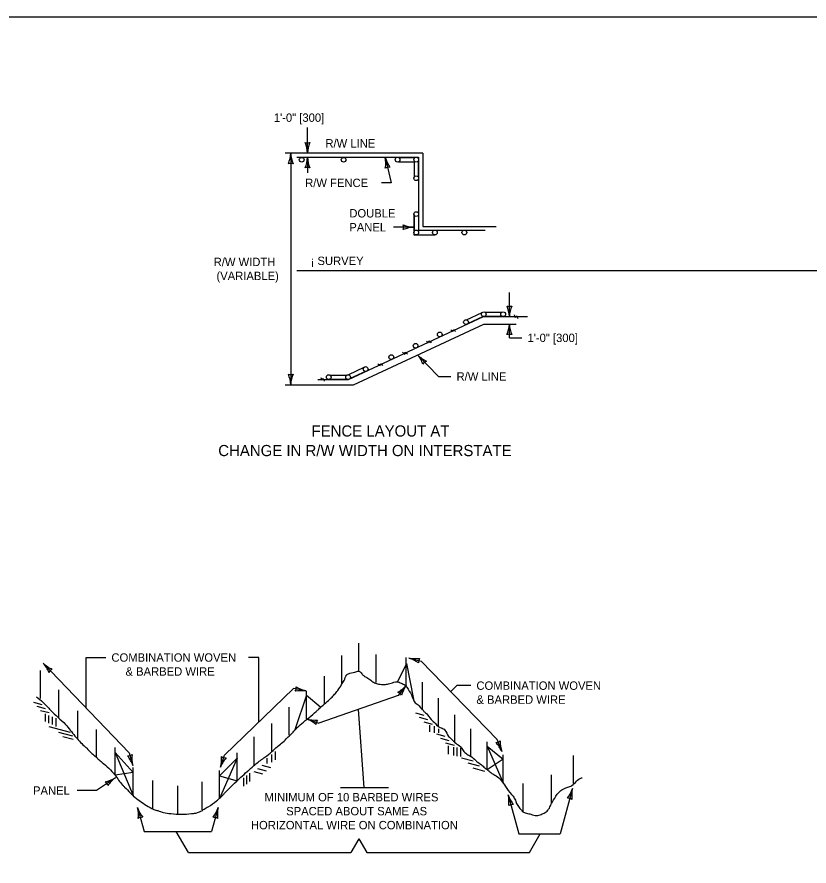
# Model space of a CAD drawing. Extents: x 49991.4 to 50021, y 49987.6 to 50011.4.
# Drawn here: x 50005.57 to 50011.24, y 49992.92 to 49999 of the extents above; entities that cross this region are included whole.
import ezdxf

# ---------------------------------------------------------------- set-up
doc = ezdxf.new("R2010")
doc.units = 0
for name, color, linetype in [('Level 1', 7, 'Continuous'), ('Level 2', 7, 'Continuous'), ('Level 3', 7, 'Continuous'), ('Level 5', 7, 'Continuous')]:
    doc.layers.add(name, color=color, linetype=linetype)

msp = doc.modelspace()

# ---------------------------------------------------------------- linework, layer by layer
at = {"layer": 'Level 1'}
for p, q in [((50008.4738, 49998.0252), (50007.4893, 49998.0252)), ((50008.4738, 49998.0252), (50008.4738, 49997.5002)), ((50007.5736, 49997.9952), (50008.4436, 49997.9952)), ((50008.3006, 49997.9631), (50008.4119, 49997.9631)), ((50008.3015, 49997.9927), (50008.4179, 49997.9927)), ((50008.4119, 49997.9631), (50008.4119, 49997.8539)), ((50008.4413, 49997.9698), (50008.4413, 49997.8545)), ((50008.4436, 49997.9952), (50008.4436, 49997.4741)), ((50008.4098, 49997.5899), (50008.4098, 49997.4402)), ((50008.4113, 49997.5827), (50008.4113, 49997.464)), ((50008.4436, 49997.4741), (50008.9198, 49997.4741)), ((50008.4738, 49997.5002), (50008.4738, 49997.5002)), ((50008.4738, 49997.5002), (50008.9988, 49997.5002)), ((50008.4098, 49997.4402), (50008.5609, 49997.4402)), ((50008.4316, 49997.441), (50008.5555, 49997.441)), ((50008.7868, 49996.8322), (50008.8978, 49996.884)), ((50008.918, 49996.8868), (50009.0402, 49996.8868)), ((50007.9422, 49996.4052), (50008.9072, 49996.8552)), ((50007.9779, 49996.3681), (50008.9091, 49996.8024)), ((50008.7965, 49996.806), (50008.904, 49996.8561)), ((50008.9072, 49996.8552), (50009.2216, 49996.8552)), ((50008.9091, 49996.8024), (50009.1424, 49996.8024)), ((50008.9183, 49996.8575), (50009.0399, 49996.8575)), ((50007.809, 49996.4368), (50007.9311, 49996.4368)), ((50008.0523, 49996.4908), (50007.9416, 49996.4392)), ((50008.0631, 49996.4637), (50007.9533, 49996.4125)), ((50007.7238, 49996.4052), (50007.9422, 49996.4052)), ((50007.8096, 49996.4077), (50007.9316, 49996.4077)), ((50007.4893, 49996.3681), (50007.9779, 49996.3681)), ((50008.0156, 49994.3196), (50008.0156, 49994.5196)), ((50007.8945, 49994.2304), (50007.8945, 49994.4304)), ((50008.1394, 49994.237), (50008.1394, 49994.437)), ((50008.3562, 49994.3731), (50008.2927, 49994.2424)), ((50008.3556, 49994.2174), (50008.3556, 49994.4174)), ((50008.3562, 49994.3731), (50008.4071, 49994.1182)), ((50005.7392, 49994.1234), (50005.7392, 49994.3234)), ((50007.7696, 49994.0834), (50007.7696, 49994.2834)), ((50008.4711, 49994.0403), (50008.4711, 49994.2403)), ((50005.8719, 49993.9843), (50005.8719, 49994.1843)), ((50007.6426, 49994.1477), (50007.5591, 49993.9001)), ((50007.6426, 49993.9766), (50007.6426, 49994.1766)), ((50007.6426, 49994.1477), (50007.7448, 49994.0622)), ((50008.5856, 49993.9259), (50008.5856, 49994.1259)), ((50005.6896, 49994.097), (50005.7502, 49994.0808)), ((50005.7132, 49994.0676), (50005.7738, 49994.0514)), ((50005.7407, 49994.0381), (50005.8013, 49994.0219)), ((50005.7761, 49993.9585), (50005.7761, 49994.0126)), ((50006.0065, 49993.8342), (50006.0065, 49994.0342)), ((50007.5187, 49993.8601), (50007.5187, 49994.0601)), ((50008.4203, 49994.0195), (50008.4809, 49994.0033)), ((50008.703, 49993.8057), (50008.703, 49994.0057)), ((50005.7987, 49993.9477), (50005.7987, 49994.0018)), ((50005.8243, 49993.9369), (50005.8243, 49993.991)), ((50005.8518, 49993.9231), (50005.8518, 49993.9821)), ((50007.3937, 49993.7435), (50007.3937, 49993.9435)), ((50008.4478, 49993.99), (50008.5084, 49993.9738)), ((50008.4812, 49993.9566), (50008.5418, 49993.9404)), ((50005.7996, 49993.923), (50005.9516, 49993.8824)), ((50006.1392, 49993.7008), (50006.1392, 49993.9008)), ((50008.5207, 49993.932), (50008.5207, 49993.8848)), ((50008.5541, 49993.9242), (50008.5541, 49993.877)), ((50008.5855, 49993.9065), (50008.5855, 49993.877)), ((50008.8174, 49993.7061), (50008.8174, 49993.9061)), ((50005.8694, 49993.8818), (50005.9694, 49993.8551)), ((50005.8989, 49993.8514), (50005.9731, 49993.8316)), ((50007.2688, 49993.6477), (50007.2688, 49993.8477)), ((50008.5716, 49993.8702), (50008.6322, 49993.854)), ((50008.5991, 49993.8388), (50008.6597, 49993.8226)), ((50006.2738, 49993.5735), (50006.2738, 49993.7735)), ((50008.6365, 49993.8053), (50008.6971, 49993.7891)), ((50008.6542, 49993.7855), (50008.6542, 49993.7246)), ((50008.6935, 49993.7758), (50008.6935, 49993.7149)), ((50008.7171, 49993.7718), (50008.7171, 49993.7109)), ((50008.7427, 49993.7698), (50008.7427, 49993.7089)), ((50008.9329, 49993.6134), (50008.9329, 49993.8134)), ((50008.9329, 49993.7829), (50009.0483, 49993.6892)), ((50008.9329, 49993.7829), (50009.0483, 49993.5197)), ((50006.2728, 49993.7371), (50006.4016, 49993.593)), ((50006.2728, 49993.7371), (50006.4026, 49993.4294)), ((50007.1458, 49993.535), (50007.1458, 49993.735)), ((50007.3907, 49993.7217), (50007.3907, 49993.6666)), ((50007.4182, 49993.7443), (50007.4182, 49993.6834)), ((50009.0483, 49993.5197), (50009.0483, 49993.7197)), ((50009.5514, 49993.5159), (50009.5514, 49993.7159)), ((50007.0188, 49993.5692), (50007.1458, 49993.6956)), ((50007.1458, 49993.6956), (50007.0188, 49993.4086)), ((50007.3228, 49993.645), (50007.3834, 49993.6288)), ((50007.3582, 49993.6971), (50007.3582, 49993.6587)), ((50008.7512, 49993.6994), (50008.8347, 49993.6771)), ((50008.7969, 49993.6628), (50008.8759, 49993.6417)), ((50009.0483, 49993.6892), (50008.9329, 49993.6134)), ((50006.4016, 49993.593), (50006.2738, 49993.5735)), ((50006.4026, 49993.4294), (50006.4026, 49993.6294)), ((50007.0188, 49993.4086), (50007.0188, 49993.6086)), ((50007.2354, 49993.589), (50007.2354, 49993.5281)), ((50007.2658, 49993.5998), (50007.3264, 49993.5836)), ((50007.2923, 49993.6224), (50007.3529, 49993.6062)), ((50008.831, 49993.6265), (50008.9153, 49993.604)), ((50006.5421, 49993.3363), (50006.5421, 49993.5363)), ((50006.8948, 49993.3274), (50006.8948, 49993.5274)), ((50007.0188, 49993.5692), (50007.1458, 49993.535)), ((50007.1921, 49993.5566), (50007.1921, 49993.4957)), ((50007.2118, 49993.5713), (50007.2118, 49993.5104)), ((50009.3942, 49993.3764), (50009.3942, 49993.5764)), ((50006.7209, 49993.2989), (50006.7209, 49993.4989)), ((50009.1908, 49993.3153), (50009.1908, 49993.5153))]:
    msp.add_line(p, q, dxfattribs=at)
msp.add_lwpolyline([(49999.3835, 49998.9992), (50016.7501, 49998.9992), (50016.7501, 49987.7988), (49999.3835, 49987.7988)], close=True, dxfattribs=at)
for centre in [(50007.6075, 49997.978), (50007.9072, 49997.9778), (50008.2929, 49997.9783), (50008.4267, 49997.9783), (50008.4267, 49997.8456), (50008.4267, 49997.5888), (50008.4268, 49997.4572), (50008.5601, 49997.4572), (50008.7709, 49997.4572), (50008.9097, 49996.872), (50009.0484, 49996.8721), (50008.7828, 49996.8158), (50008.5954, 49996.7277), (50008.4222, 49996.6472), (50008.2484, 49996.5658), (50008.065, 49996.4805), (50007.8008, 49996.4223), (50007.9396, 49996.4226)]:
    msp.add_circle(centre, 0.0169, dxfattribs=at)
for points in [[(50009.1272, 49996.8678), (50009.1356, 49996.8509), (50009.1356, 49996.8593), (50009.1442, 49996.8509), (50009.1442, 49996.8593), (50009.1526, 49996.8423)], [(50008.6741, 49996.7611), (50008.6886, 49996.7494), (50008.6853, 49996.7571), (50008.6966, 49996.753), (50008.693, 49996.7607), (50008.7077, 49996.749)], [(50008.5005, 49996.6804), (50008.5154, 49996.6684), (50008.5118, 49996.6762), (50008.523, 49996.672), (50008.5194, 49996.6798), (50008.5343, 49996.668)], [(50008.3295, 49996.6006), (50008.3444, 49996.5889), (50008.3408, 49996.5966), (50008.352, 49996.5925), (50008.3484, 49996.6002), (50008.3633, 49996.5885)], [(50008.1533, 49996.5181), (50008.1681, 49996.5061), (50008.1645, 49996.5138), (50008.1759, 49996.5097), (50008.1723, 49996.5174), (50008.1872, 49996.5057)], [(50007.7435, 49996.4196), (50007.7517, 49996.4026), (50007.7517, 49996.4112), (50007.7604, 49996.4026), (50007.7604, 49996.4112), (50007.7687, 49996.3942)], [(50005.7117, 49994.1355), (50005.7569, 49994.0975), (50005.8117, 49994.0386), (50005.9185, 49993.9372), (50005.9857, 49993.8547), (50006.052, 49993.7841), (50006.0703, 49993.7678), (50006.1058, 49993.7306), (50006.1366, 49993.7053), (50006.152, 49993.6899), (50006.1809, 49993.6663), (50006.2712, 49993.5766), (50006.3269, 49993.5042), (50006.3413, 49993.4897), (50006.3807, 49993.448), (50006.4134, 49993.4172), (50006.4616, 49993.3819), (50006.5097, 49993.3501), (50006.5647, 49993.3248), (50006.5782, 49993.3211), (50006.6197, 49993.3076), (50006.6709, 49993.3003), (50006.7481, 49993.2948), (50006.8187, 49993.2994), (50006.8496, 49993.3039), (50006.8768, 49993.3129), (50006.8932, 49993.3202), (50006.9097, 49993.3319), (50006.9388, 49993.3491), (50006.998, 49993.3908), (50007.0271, 49993.4152), (50007.0416, 49993.4297), (50007.0562, 49993.446), (50007.1728, 49993.5592), (50007.264, 49993.6416), (50007.329, 49993.6923), (50007.3591, 49993.7131), (50007.4455, 49993.7891), (50007.4823, 49993.819), (50007.5105, 49993.848), (50007.5387, 49993.8743), (50007.5659, 49993.9041), (50007.6076, 49993.944), (50007.7115, 49994.0309), (50007.729, 49994.0472), (50007.7426, 49994.059), (50007.8183, 49994.1269), (50007.8426, 49994.1531), (50007.865, 49994.1812), (50007.8932, 49994.2228), (50007.901, 49994.2382), (50007.9107, 49994.2518), (50007.9293, 49994.2917), (50007.9419, 49994.3007), (50007.9874, 49994.3125), (50008.0164, 49994.3179), (50008.0318, 49994.307), (50008.0424, 49994.2943), (50008.0578, 49994.2817), (50008.0867, 49994.2644), (50008.1011, 49994.2536), (50008.1156, 49994.2427), (50008.1426, 49994.23), (50008.1696, 49994.2246), (50008.2005, 49994.2237), (50008.2295, 49994.2282), (50008.2673, 49994.239), (50008.2876, 49994.2427), (50008.304, 49994.239), (50008.3329, 49994.2263), (50008.3464, 49994.2182), (50008.3598, 49994.2037), (50008.3694, 49994.1892), (50008.3982, 49994.1358), (50008.4039, 49994.1204), (50008.4182, 49994.0932), (50008.4471, 49994.0715), (50008.4577, 49994.057), (50008.4721, 49994.0434), (50008.4855, 49994.0271), (50008.499, 49994.0153), (50008.5336, 49993.9736), (50008.5634, 49993.9446), (50008.5749, 49993.931), (50008.5922, 49993.9184), (50008.6057, 49993.9138), (50008.6317, 49993.8975), (50008.6586, 49993.8522), (50008.6711, 49993.8395), (50008.7009, 49993.8097), (50008.7365, 49993.7843), (50008.75, 49993.7716), (50008.7566, 49993.7571), (50008.7672, 49993.7444), (50008.7961, 49993.72), (50008.8105, 49993.7136), (50008.8423, 49993.6901)], [(50008.8423, 49993.6901), (50008.8586, 49993.6729), (50008.8933, 49993.6484), (50008.9164, 49993.6276), (50008.9385, 49993.6113), (50008.9674, 49993.5877), (50008.9973, 49993.5705), (50009.0645, 49993.4944), (50009.1077, 49993.4373), (50009.1192, 49993.4246), (50009.1279, 49993.4092), (50009.1355, 49993.3948), (50009.1412, 49993.3794), (50009.1585, 49993.3504), (50009.1796, 49993.3232), (50009.194, 49993.3096), (50009.2066, 49993.3042), (50009.2403, 49993.2969), (50009.3128, 49993.2897), (50009.3273, 49993.2987), (50009.3409, 49993.3032), (50009.368, 49993.3232), (50009.3787, 49993.3395), (50009.3944, 49993.3711), (50009.4256, 49993.4237), (50009.447, 49993.4517), (50009.477, 49993.4744), (50009.4964, 49993.4834), (50009.5109, 49993.4888), (50009.5245, 49993.4934), (50009.54, 49993.5015), (50009.6079, 49993.5549), (50009.6137, 49993.5567)]]:
    msp.add_spline(points, degree=3, dxfattribs=at)
at = {"layer": 'Level 3'}
for p, q in [((50007.6488, 49998.0252), (50007.6488, 49998.209)), ((50007.5293, 49998.0252), (50007.5293, 49996.3681)), ((50007.6488, 49997.9952), (50007.6488, 49997.8837)), ((50008.2055, 49997.9952), (50008.2465, 49997.8122)), ((50008.2465, 49997.8122), (50008.1789, 49997.8122)), ((50008.4098, 49997.4948), (50008.2651, 49997.4948)), ((50009.0927, 49996.8552), (50009.0927, 49997.0287)), ((50009.0927, 49996.7035), (50009.0927, 49996.8024)), ((50009.0927, 49996.7035), (50009.1826, 49996.7035)), ((50008.4367, 49996.5821), (50008.5859, 49996.4272)), ((50008.5859, 49996.4272), (50008.6752, 49996.4272)), ((50005.7591, 49994.3758), (50006.3732, 49993.7334)), ((50006.0661, 49994.0546), (50006.0661, 49994.4163)), ((50006.0661, 49994.4163), (50006.207, 49994.4163)), ((50007.3019, 49994.4163), (50007.2278, 49994.4163)), ((50007.3019, 49993.9564), (50007.3019, 49994.4163)), ((50008.3734, 49994.4128), (50008.4632, 49994.3895)), ((50008.4632, 49994.3895), (50009.0059, 49993.8299)), ((50007.0559, 49993.7188), (50007.5479, 49994.1941)), ((50007.6275, 49994.1794), (50007.5479, 49994.1941)), ((50008.3556, 49994.2174), (50008.2983, 49994.1445)), ((50008.7172, 49994.2152), (50008.6741, 49994.1721)), ((50008.8172, 49994.2152), (50008.7172, 49994.2152)), ((50008.2983, 49994.1445), (50007.7308, 49993.9478)), ((50008.0107, 49994.0449), (50008.0521, 49993.4872)), ((50007.6426, 49993.9766), (50007.7308, 49993.9478)), ((50009.0392, 49993.7434), (50009.0059, 49993.8299)), ((50006.3732, 49993.7334), (50006.4002, 49993.6447)), ((50007.0263, 49993.6309), (50007.0559, 49993.7188)), ((50006.275, 49993.5557), (50006.1406, 49993.4647)), ((50006.1406, 49993.4647), (50006.0029, 49993.4647)), ((50007.8854, 49993.4872), (50008.2281, 49993.4872)), ((50009.5437, 49993.4783), (50009.4568, 49993.1538)), ((50009.0846, 49993.4344), (50009.1598, 49993.1538)), ((50006.4345, 49993.3422), (50006.4802, 49993.1715)), ((50007.0093, 49993.3422), (50006.9636, 49993.1715)), ((50006.4802, 49993.1715), (50006.9636, 49993.1715)), ((50006.7979, 49993.0207), (50006.7107, 49993.1717)), ((50009.1598, 49993.1538), (50009.4568, 49993.1538)), ((50009.2362, 49993.0207), (50009.313, 49993.1537)), ((50008.017, 49993.119), (50007.9602, 49993.0207)), ((50008.017, 49993.119), (50008.0738, 49993.0207)), ((50006.7979, 49993.0207), (50007.9602, 49993.0207)), ((50008.0738, 49993.0207), (50009.2362, 49993.0207))]:
    msp.add_line(p, q, dxfattribs=at)
for centre, radius, start, end in [((50007.6488, 49998.1534), 0.0548, 252.13882, 287.86118), ((50007.4161, 49998.0137), 0.233, 2.82731, 22.07716), ((50007.8709, 49998.0161), 0.2223, 157.45601, 177.63952), ((50007.3071, 49998.0344), 0.2223, 337.45601, 357.63952), ((50007.762, 49998.0367), 0.233, 182.82731, 202.07716), ((50007.4266, 49998.0044), 0.2223, 337.45601, 357.63952), ((50007.8815, 49998.0067), 0.233, 182.82731, 202.07716), ((50007.9867, 49997.9556), 0.2223, 350.07533, 10.25884), ((50008.4301, 49998.0573), 0.233, 195.44663, 214.69648), ((50007.5293, 49997.897), 0.0548, 72.13882, 107.86118), ((50007.6488, 49997.867), 0.0548, 72.13882, 107.86118), ((50008.2335, 49997.8701), 0.0548, 84.75814, 120.4805), ((50008.419, 49997.7169), 0.2223, 247.45601, 267.63952), ((50008.2816, 49997.4948), 0.0548, 342.13882, 17.86118), ((50008.4213, 49997.2621), 0.233, 92.82731, 112.07716), ((50009.0927, 49996.9834), 0.0548, 252.13882, 287.86118), ((50008.86, 49996.8437), 0.233, 2.82731, 22.07716), ((50009.3148, 49996.8461), 0.2223, 157.45601, 177.63952), ((50008.8705, 49996.8116), 0.2223, 337.45601, 357.63952), ((50009.3254, 49996.8139), 0.233, 182.82731, 202.07716), ((50009.0927, 49996.6742), 0.0548, 72.13882, 107.86118), ((50008.2651, 49996.4407), 0.2223, 19.3171, 39.50061), ((50008.6023, 49996.746), 0.233, 224.6884, 243.93825), ((50008.5223, 49996.4866), 0.0548, 113.99991, 149.72227), ((50007.5293, 49996.4963), 0.0548, 252.13882, 287.86118), ((50007.2966, 49996.3566), 0.233, 2.82731, 22.07716), ((50007.7514, 49996.359), 0.2223, 157.45601, 177.63952), ((50005.5922, 49994.2289), 0.2223, 21.16546, 41.34897), ((50005.9194, 49994.5449), 0.233, 226.53676, 245.78661), ((50008.3089, 49994.2), 0.2223, 52.95255, 73.13606), ((50008.4205, 49994.641), 0.233, 258.32385, 277.5737), ((50008.4975, 49994.3807), 0.0548, 147.63536, 183.35772), ((50005.8477, 49994.2831), 0.0548, 115.84827, 151.57063), ((50007.513, 49994.2004), 0.0548, 331.67241, 7.39477), ((50007.6884, 49994.3939), 0.2223, 236.9896, 257.17311), ((50008.1866, 49994.3619), 0.2223, 299.28829, 319.4718), ((50008.5457, 49994.0826), 0.233, 144.65959, 163.90944), ((50007.6081, 49993.9462), 0.233, 82.3609, 101.61075), ((50008.2764, 49994.1166), 0.0548, 33.9711, 69.69346), ((50007.565, 49993.7683), 0.2223, 49.39146, 69.57497), ((50007.7038, 49994.2014), 0.233, 254.76276, 274.01261), ((50007.7645, 49993.9368), 0.0548, 144.07427, 179.79663), ((50008.9931, 49993.863), 0.0548, 273.19606, 308.91842), ((50008.8261, 49993.6491), 0.233, 23.88455, 43.1344), ((50009.2498, 49993.8147), 0.2223, 178.51325, 198.69676), ((50006.3628, 49993.7674), 0.0548, 269.07011, 304.79247), ((50006.1809, 49993.5659), 0.233, 19.7586, 39.00845), ((50006.6154, 49993.7006), 0.2223, 174.3873, 194.57081), ((50006.8021, 49993.6942), 0.233, 344.22868, 3.47853), ((50007.0672, 49993.7524), 0.0548, 233.54019, 269.26255), ((50007.2339, 49993.5514), 0.2223, 138.85738, 159.04089), ((50006.1594, 49993.7456), 0.2223, 281.14608, 301.32959), ((50006.1683, 49993.4846), 0.0548, 15.82889, 51.55125), ((50006.4136, 49993.3684), 0.233, 126.51738, 145.76723), ((50009.3315, 49993.5446), 0.2223, 322.46461, 342.64812), ((50009.7715, 49993.4292), 0.233, 167.83591, 187.08576), ((50008.8677, 49993.3857), 0.2223, 352.45841, 12.64192), ((50009.3064, 49993.5057), 0.233, 197.82971, 217.07956), ((50009.5105, 49993.3544), 0.0548, 57.14742, 92.86978), ((50006.2175, 49993.2936), 0.2223, 352.44483, 12.62834), ((50006.6563, 49993.4135), 0.233, 197.81613, 217.06598), ((50006.7971, 49993.4085), 0.2223, 322.46719, 342.6507), ((50007.2371, 49993.2931), 0.233, 167.83849, 187.08834), ((50009.1178, 49993.3105), 0.0548, 87.14122, 122.86358), ((50006.4676, 49993.2183), 0.0548, 87.12764, 122.85), ((50006.9761, 49993.2183), 0.0548, 57.15, 92.87236)]:
    msp.add_arc(centre, radius, start, end, dxfattribs=at)
at = {"layer": 'Level 5'}
msp.add_line((50007.5738, 49997.1846), (50013.8507, 49997.1846), dxfattribs=at)

# ---------------------------------------------------------------- texts
at = {"layer": 'Level 2'}
for s, height, p in [('1\'-0" [300]', 0.06, (50007.4083, 49998.249)), ('R/W LINE', 0.06, (50007.7772, 49998.0652)), ('R/W FENCE', 0.06, (50007.6323, 49997.7822)), ('DOUBLE', 0.06, (50007.9483, 49997.5648)), ('PANEL', 0.06, (50007.9483, 49997.4648)), ('¡ SURVEY', 0.06, (50007.6714, 49997.2246)), ('R/W WIDTH', 0.06, (50006.9782, 49997.2167)), ('(VARIABLE)', 0.06, (50006.9981, 49997.1167)), ('1\'-0" [300]', 0.06, (50009.2226, 49996.6735)), ('R/W LINE', 0.06, (50008.7152, 49996.3972)), ('FENCE LAYOUT AT', 0.08, (50007.6776, 49995.9971)), ('CHANGE IN R/W WIDTH ON INTERSTATE', 0.08, (50007.0109, 49995.8571)), ('COMBINATION WOVEN', 0.06, (50006.247, 49994.3863)), ('& BARBED WIRE', 0.06, (50006.3476, 49994.2863)), ('COMBINATION WOVEN', 0.06, (50008.8572, 49994.1852)), ('& BARBED WIRE', 0.06, (50008.8572, 49994.0852)), ('PANEL', 0.06, (50005.6861, 49993.4347)), ('MINIMUM OF 10 BARBED WIRES', 0.06, (50007.3418, 49993.3872)), ('SPACED ABOUT SAME AS', 0.06, (50007.4967, 49993.2872)), ('HORIZONTAL WIRE ON COMBINATION', 0.06, (50007.2445, 49993.1872))]:
    msp.add_text(s, height=height, dxfattribs=at).set_placement(p)

doc.saveas('drawing.dxf')
